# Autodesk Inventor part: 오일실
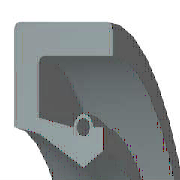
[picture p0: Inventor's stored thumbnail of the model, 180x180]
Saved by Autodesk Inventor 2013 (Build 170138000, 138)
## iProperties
Created: 2015-10
Part Number: 오일실
Material: 고무
Description: 오일-실
Document SubType Name: Modeling
Standard: KS B 2804
Designer: mdu
Standards Organization: KS
Language: ko-KR
Size Designation: S - 25 38 8
Categories: <MemberInstance><Categories><Category DisplayName="샤프트 부품" InternalName="7f7aeb1f-a693-4053-b835-cee3144e0d98" Mnemonic="SHFT"><Category DisplayName="실링" Intern
Density: 0.93 g/cm^3
Mass: 2.23721 g
Surface Area: 37.0166 cm^2
Volume: 2.4056 cm^3
IsCustomPart: 1
Author: mdu
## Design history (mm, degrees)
revolve "본체" stored, may be unused: angle "d17" = 90 deg
revolve "스프링1" stored, may be unused: angle "d18" = 90 deg
body "Solid1"
sketch "스케치1"
  geometry: L1 (0, 19)-(8, 19); L2 (8, 19)-(8, 17.75); L3 (8, 17.75)-(1.75, 17.75); L4 (0, 19)-(0, 14.6); L5 (0, 14.6)-(1.75, 14.25); L6 (1.75, 14.25)-(4.9, 12.5); L7 (4.9, 12.5)-(0, 12.5); L8 (6.3, 13.375)-(6.3, 14.6); L9 (0, 0)-(9.586, 0) reference; L10 (4.9, 12.5)-(6.3, 13.375); L11 (0, 18)-(0, -3) reference; L12 (-1.917, 0)-(11.503, 0) reference; L13 (4.2, 14.6)-(1.75, 15.09); L14 (1.75, 15.09)-(1.75, 17.75); L15 (6.3, 14.6)-(5.6, 14.6); C1 r 0.455 at (4.9, 14.6); A1 r 0.7 centre (4.9, 14.6) between (5.6, 14.6) and (4.2, 14.6)
  constraints: 26 end point, 5 horizontal alignment, 4 perpendicular, 2 centre point, 2 collinear, 2 horizontal, 2 parallel, 2 point on circle, 2 point on line, 2 vertical alignment, 1 coincident
  dimensions: "d0" = 38 diameter of L1 L9 (= SD2); "d1" = 26.75 diameter of L8.start L9 (= ABDM); "d2" = 1.25 distance of L1.end L2.end (computed from SD); "d3" = 0.91 diameter of C1 (= SPDI); "d4" = 1.4 diameter of A1 (= SPDA); "d5" = 25 diameter of L6.end L9 (= NND); "d6" = 28.5 diameter of L5.end L9 (= TKDM); "d7" = 29.2 diameter of L4.end L9 (= HLDM); "d8" = 4.9 distance from line of C1.centre L4 (= SPDST); "d9" = 6.3 distance between parallel lines of L8 L4 (= SDI); "d10" = 8 distance between parallel lines of L2 L4 (= SWDT); "d12" = 1.75 distance between parallel lines of L14 L4 (= SD)
fillet "모깎기1" dims "d11" = 0.3 (= RR)
other parameters: "SD2" = 38 [user parameter; used in 1 equation term], "SWDT" = 8 [user parameter; used in 1 equation term], "RR" = 0.3 [user parameter; used in 1 equation term], "SD" = 1.75 [user parameter; used in 2 equation terms], "NND" = 25 [user parameter; used in 1 equation term], "SPDA" = 1.4 [user parameter; used in 1 equation term], "SPDI" = 0.91 [user parameter; used in 1 equation term], "TKDM" = 28.5 [user parameter; used in 1 equation term], "HLDM" = 29.2 [user parameter; used in 1 equation term], "ABDM" = 26.75 [user parameter; used in 1 equation term], "SDI" = 6.3 [user parameter; used in 1 equation term], "SPDST" = 4.9 [user parameter; used in 1 equation term], "d13" = 0, "d14" = 0, "d15" = 0, "LAB" = 0.35 [user parameter]
